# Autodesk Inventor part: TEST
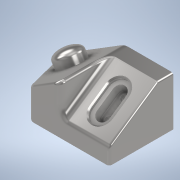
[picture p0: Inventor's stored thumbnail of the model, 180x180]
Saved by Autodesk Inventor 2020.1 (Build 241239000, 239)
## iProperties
Created: 2019-11
Part Number: TEST
Material: Stainless Steel, 440C
Document SubType Name: Modeling
Designer: Synergysoft Dell02
Density: 7.75 g/cm^3
Appearance: Semi-Polished
Author: Synergysoft Dell02
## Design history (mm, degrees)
sketch "Sketch1"
  geometry: L1 (0, 0)-(-62, 0); L2 (-62, 0)-(-62, -50); L3 (-62, -50)-(18, -50); L4 (18, -50)-(18, -38); L5 (18, -38)-(0, 0)
  constraints: 10 end point, 3 perpendicular, 1 horizontal
  dimensions: "d0" = 62 distance of L1.start L1.end; "d1" = 50 distance of L1.end L2.end; "d2" = 80 distance of L2.end L3.end; "d3" = 12 distance of L3.end L4.end
extrude "Extrusion1" new body sketch "Sketch1" distance "d4" = 38; taper "d5" = 0 deg
workplane "Work Plane3"
workplane "Work Plane4"
workaxis "Work Axis1"
feature "Sculpt1"
  workplane "Work Plane6"
workplane "Work Plane7"
  workaxis "Work Axis4"
sketch "Sketch4"
  geometry: L1 (-50, 0)-(-50, 49.396) reference; L2 (-50, 49.396)-(-38, 49.396) reference; L3 (-38, 49.396)-(0, 28.226) reference; L4 (0, 28.226)-(0, 0) reference; L5 (0, 0)-(-38, 0) reference; L6 (-38, 0)-(-50, 0) reference; L7 (-50, 0)-(-50, 49.396) reference; L8 (0, 28.226)-(0, 0) reference; L9 (0, 0)-(-38, 0) reference; L10 (-38, 0)-(-50, 0) reference; L11 (-50, 49.396)-(-38, 49.396) reference; L12 (-38, 49.396)-(0, 28.226) reference; 1 further point
extrude "Extrusion4" cut sketch "Sketch4" extent not by distance; stored distance "d16" = 14.696; taper "d17" = 0 deg
sketch "Sketch5"
  geometry: L1 (19, 30.522)-(19, 15.522); L2 (14, 30.522)-(14, 15.522); L3 (24, 15.522)-(24, 30.522); L4 (38, 46.043)-(0, 46.043) reference; L5 (38, 0)-(38, 46.043) reference; L6 (11, 30.522)-(11, 15.522); L7 (27, 15.522)-(27, 30.522); A1 r 5 centre (19, 30.522) between (24, 30.522) and (14, 30.522); A2 r 5 centre (19, 15.522) between (14, 15.522) and (24, 15.522); A3 r 8 centre (19, 15.522) between (11, 15.522) and (27, 15.522); A4 r 8 centre (19, 30.522) between (27, 30.522) and (11, 30.522); 4 further points
  constraints: 12 end point, 8 point on circle, 4 centre point, 4 tangent, 3 midpoint, 2 parallel, 1 horizontal alignment, 1 vertical, 1 vertical alignment, 3 other
  dimensions: "d23" = 15 distance of L1.start L1.end; "d24" = 5 radius of A1; "d25" = 3 radial gap between concentric circles of A1 A4
extrude "Extrusion5" cut sketch "Sketch5" distance "d26" = 10; taper "d27" = 0 deg
extrude "Extrusion6" cut sketch "Sketch5" distance "d28" = 3; taper "d29" = 0 deg
fillet "Fillet1" dims "d18" = 5
fillet "Fillet2" dims "d19" = 5
fillet "Fillet3" dims "d20" = 10
fillet "Fillet4" dims "d21" = 2
fillet "Fillet5" dims "d22" = 2
chamfer "Chamfer1" distance "d30" = 1; stored, may be unused: second distance "d31" = 2, angle "d32" = 45 deg
sketch "Sketch6"
  geometry: A1 r 5 centre (19, 30.522) between (24, 30.522) and (14, 30.522) reference; A2 r 5 centre (19, 15.522) between (14, 15.522) and (24, 15.522) reference; 3 further points
  constraints: 2 coincident
hole "Hole1" sketch "Sketch6" at (19, 30.522), (19, 15.522) diameter "d33" = 3; stored, may be unused: countersink angle "d37" = 90 deg, drill point angle "d39" = 118 deg; dims "d34" = 6, "d35" = 5, "d36" = 2, "d38" = 8
sketch "Sketch7"
  geometry: L1 (-48.282, 50)-(-2.845, 50) reference; L2 (-49.983, 50)-(-49.983, 39.124) reference; C1 r 10 at (-24.983, 30); 1 further point
  constraints: 1 centre point
  dimensions: "d40" = 20 diameter of C1; "d41" = 20 distance from line of C1.centre L1; "d42" = 25 distance from line of C1.centre L2
extrude "Extrusion7" join sketch "Sketch7" distance "d43" = 5; taper "d44" = 0 deg
workplane "Work Plane8"
sketch "Sketch8"
  geometry: C1 r 10 at (0, 0) reference; 1 further point
loft "Loft1" sketch "Sketch8" dims "d46" = 10, "d47" = 90 deg, "d48" = 10, "d49" = 90 deg
  node "Edges1"
workplane "Work Plane1"
sketch "Sketch2"
  geometry: L1 (0, 12)-(38, 38); L2 (38, 38)-(0, 38) reference; L3 (38, 38)-(38, 45.681); L4 (38, 45.681)-(-14.226, 45.681); L5 (-14.226, 45.681)-(-14.226, 12); L6 (-14.226, 12)-(0, 12); L7 (50, 0)-(50, 38) reference; 1 further point
  constraints: 10 end point, 3 perpendicular, 1 point on line, 1 vertical
  dimensions: "d7" = 12 distance of point (0, 0) L1.start; "d8" = 12 distance from line of L7 L1.end
extrude "Extrusion2" cut sketch "Sketch2" extent not by distance; stored distance "d9" = 38; taper "d10" = 0 deg
workpoint "Work Point1"
workplane "Work Plane2"
sketch "Sketch3"
  geometry: L1 (0, 0)-(11.837, 64.745) reference; L2 (44.944, 0)-(0, 0) reference; 1 further point; 1 other entity
  constraints: 1 other
extrude "Extrusion3" cut sketch "Sketch3" extent not by distance; stored distance "d11" = 39.85; taper "d12" = 0 deg
body "Solid1"
workplane "Work Plane5"
workaxis "Work Axis2"
workaxis "Work Axis3"
node "Projected Loop1"
node "Project Cut Edges1"
node "Project Cut Edges2"
node "Project Cut Edges3"
other parameters: "d6" = -38, "d13" = -38, "d14" = -12, "d15" = -12, "d45" = 5
